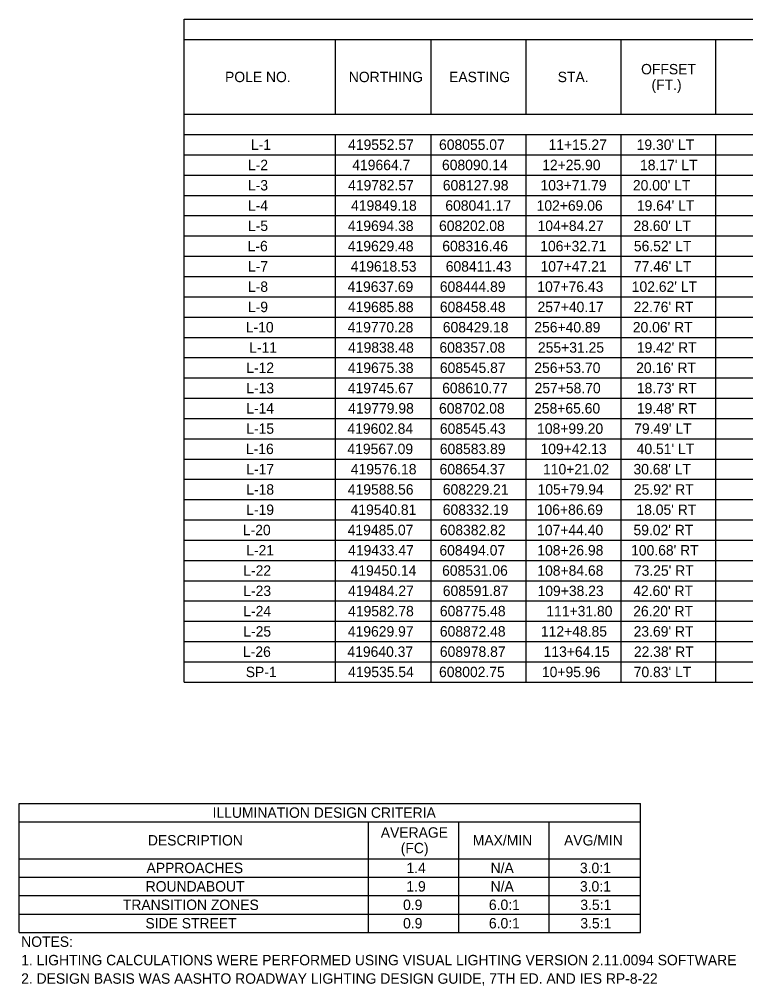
# Model space of a CAD drawing. Extents: x 0.17 to 2.79, y 0.05 to 1.72.
# Drawn here: x 0.169 to 0.862, y 0.144 to 1.066 of the extents above; entities that cross this region are included whole.
import ezdxf

# ---------------------------------------------------------------- set-up
doc = ezdxf.new("R2010")
doc.units = 0
doc.layers.add('Default', color=7, linetype='Continuous')
doc.layers.add('No_Plot', color=7, linetype='Continuous')

msp = doc.modelspace()

# ---------------------------------------------------------------- linework, layer by layer
at = {"layer": 'Default'}
for p, q in [((0.32609, 1.06625), (2.52066, 1.06625)), ((0.32609, 0.43358), (0.32609, 1.06625)), ((0.32609, 1.04689), (2.52066, 1.04689)), ((0.4704, 0.97562), (0.4704, 1.04689)), ((0.56192, 0.97562), (0.56192, 1.04689)), ((0.65255, 0.97562), (0.65255, 1.04689)), ((0.74318, 0.97562), (0.74318, 1.04689)), ((0.83382, 0.97562), (0.83382, 1.04689)), ((0.32609, 0.97562), (2.52066, 0.97562)), ((0.32609, 0.95626), (2.52066, 0.95626)), ((0.4704, 0.43358), (0.4704, 0.95626)), ((0.56192, 0.43358), (0.56192, 0.95626)), ((0.65255, 0.43358), (0.65255, 0.95626)), ((0.74318, 0.43358), (0.74318, 0.95626)), ((0.83382, 0.43358), (0.83382, 0.95626)), ((0.32609, 0.9369), (2.52066, 0.9369)), ((0.32609, 0.91754), (2.52066, 0.91754)), ((0.32609, 0.89819), (2.52066, 0.89819)), ((0.32609, 0.87883), (2.52066, 0.87883)), ((0.32609, 0.85947), (2.52066, 0.85947)), ((0.32609, 0.84011), (2.52066, 0.84011)), ((0.32609, 0.82075), (2.52066, 0.82075)), ((0.32609, 0.80139), (2.52066, 0.80139)), ((0.32609, 0.78203), (2.52066, 0.78203)), ((0.32609, 0.76268), (2.52066, 0.76268)), ((0.32609, 0.74332), (2.52066, 0.74332)), ((0.32609, 0.72396), (2.52066, 0.72396)), ((0.32609, 0.7046), (2.52066, 0.7046)), ((0.32609, 0.68524), (2.52066, 0.68524)), ((0.32609, 0.66588), (2.52066, 0.66588)), ((0.32609, 0.64652), (2.52066, 0.64652)), ((0.32609, 0.62716), (2.52066, 0.62716)), ((0.32609, 0.60781), (2.52066, 0.60781)), ((0.32609, 0.58845), (2.52066, 0.58845)), ((0.32609, 0.56909), (2.52066, 0.56909)), ((0.32609, 0.54973), (2.52066, 0.54973)), ((0.32609, 0.53037), (2.52066, 0.53037)), ((0.32609, 0.51101), (2.52066, 0.51101)), ((0.32609, 0.49165), (2.52066, 0.49165)), ((0.32609, 0.4723), (2.52066, 0.4723)), ((0.32609, 0.45294), (2.52066, 0.45294)), ((0.32609, 0.43358), (2.52066, 0.43358)), ((0.16857, 0.31777), (0.76164, 0.31777)), ((0.16857, 0.19458), (0.16857, 0.31777)), ((0.76164, 0.19458), (0.76164, 0.31777)), ((0.16857, 0.30017), (0.76164, 0.30017)), ((0.50206, 0.19458), (0.50206, 0.30017)), ((0.5883, 0.19458), (0.5883, 0.30017)), ((0.67453, 0.19458), (0.67453, 0.30017)), ((0.16857, 0.26497), (0.76164, 0.26497)), ((0.16857, 0.24737), (0.76164, 0.24737)), ((0.16857, 0.22978), (0.76164, 0.22978)), ((0.16857, 0.21218), (0.76164, 0.21218)), ((0.16857, 0.19458), (0.76164, 0.19458))]:
    msp.add_line(p, q, dxfattribs=at)
at = {"layer": 'No_Plot'}
for p, q in [((0.32609, 1.06625), (0.32609, 1.06625)), ((0.16857, 0.31777), (0.16857, 0.31777))]:
    msp.add_line(p, q, dxfattribs=at)

# ---------------------------------------------------------------- texts
at = {"layer": 'Default'}
for s, height, p in [('POLE NO.', 0.009927, (0.36503, 1.00629)), ('NORTHING', 0.009927, (0.48321, 1.00629)), ('EASTING', 0.009927, (0.57897, 1.00629)), ('STA.', 0.009927, (0.6827, 1.00629)), ('OFFSET', 0.009927, (0.76235, 1.01374)), (' (FT.)', 0.009927, (0.76861, 0.99885)), ('L-1', 0.009927, (0.38973, 0.94162)), ('419552.57', 0.009927, (0.48255, 0.94162)), ('608055.07', 0.009927, (0.5694, 0.94162)), ('11+15.27', 0.009927, (0.67395, 0.94162)), ("19.30' LT", 0.009927, (0.75813, 0.94162)), ('L-2', 0.009927, (0.38691, 0.92226)), ('419664.7', 0.009927, (0.48653, 0.92226)), ('608090.14', 0.009927, (0.57221, 0.92226)), ('12+25.90', 0.009927, (0.66789, 0.92226)), ("18.17' LT", 0.009927, (0.76134, 0.92226)), ('L-3', 0.009927, (0.38691, 0.9029)), ('419782.57', 0.009927, (0.48255, 0.9029)), ('608127.98', 0.009927, (0.57299, 0.9029)), ('103+71.79', 0.009927, (0.66625, 0.9029)), ("20.00' LT", 0.009927, (0.75454, 0.9029)), ('L-4', 0.009927, (0.38691, 0.88354)), ('419849.18', 0.009927, (0.48536, 0.88354)), ('608041.17', 0.009927, (0.57542, 0.88354)), ('102+69.06', 0.009927, (0.66257, 0.88354)), ("19.64' LT", 0.009927, (0.75829, 0.88354)), ('L-5', 0.009927, (0.38691, 0.86418)), ('419694.38', 0.009927, (0.48231, 0.86418)), ('608202.08', 0.009927, (0.5694, 0.86418)), ('104+84.27', 0.009927, (0.66347, 0.86418)), ("28.60' LT", 0.009927, (0.75508, 0.86418)), ('L-6', 0.009927, (0.38664, 0.84483)), ('419629.48', 0.009927, (0.48231, 0.84483)), ('608316.46', 0.009927, (0.57249, 0.84483)), ('106+32.71', 0.009927, (0.66605, 0.84483)), ("56.52' LT", 0.009927, (0.75547, 0.84483)), ('L-7', 0.009927, (0.38691, 0.82547)), ('419618.53', 0.009927, (0.48513, 0.82547)), ('608411.43', 0.009927, (0.57581, 0.82547)), ('107+47.21', 0.009927, (0.66629, 0.82547)), ("77.46' LT", 0.009927, (0.75547, 0.82547)), ('L-8', 0.009927, (0.38691, 0.80611)), ('419637.69', 0.009927, (0.48204, 0.80611)), ('608444.89', 0.009927, (0.57014, 0.80611)), ('107+76.43', 0.009927, (0.66324, 0.80611)), ("102.62' LT", 0.009927, (0.75344, 0.80611)), ('L-9', 0.009927, (0.38687, 0.78675)), ('419685.88', 0.009927, (0.48231, 0.78675)), ('608458.48', 0.009927, (0.57018, 0.78675)), ('257+40.17', 0.009927, (0.66347, 0.78675)), ("22.76' RT", 0.009927, (0.75524, 0.78675)), ('L-10', 0.009927, (0.38484, 0.76739)), ('419770.28', 0.009927, (0.48216, 0.76739)), ('608429.18', 0.009927, (0.57299, 0.76739)), ('256+40.89', 0.009927, (0.66038, 0.76739)), ("20.06' RT", 0.009927, (0.75446, 0.76739)), ('L-11', 0.009927, (0.38809, 0.74803)), ('419838.48', 0.009927, (0.48255, 0.74803)), ('608357.08', 0.009927, (0.56979, 0.74803)), ('255+31.25', 0.009927, (0.66386, 0.74803)), ("19.42' RT", 0.009927, (0.75829, 0.74803)), ('L-12', 0.009927, (0.38527, 0.72867)), ('419675.38', 0.009927, (0.48231, 0.72867)), ('608545.87', 0.009927, (0.57018, 0.72867)), ('256+53.70', 0.009927, (0.66038, 0.72867)), ("20.16' RT", 0.009927, (0.75766, 0.72867)), ('L-13', 0.009927, (0.38527, 0.70931)), ('419745.67', 0.009927, (0.48231, 0.70931)), ('608610.77', 0.009927, (0.57237, 0.70931)), ('257+58.70', 0.009927, (0.66062, 0.70931)), ("18.73' RT", 0.009927, (0.75829, 0.70931)), ('L-14', 0.009927, (0.38527, 0.68996)), ('419779.98', 0.009927, (0.48255, 0.68996)), ('608702.08', 0.009927, (0.5694, 0.68996)), ('258+65.60', 0.009927, (0.66015, 0.68996)), ("19.48' RT", 0.009927, (0.75829, 0.68996)), ('L-15', 0.009927, (0.38527, 0.6706)), ('419602.84', 0.009927, (0.48192, 0.6706)), ('608545.43', 0.009927, (0.57018, 0.6706)), ('108+99.20', 0.009927, (0.66304, 0.6706)), ("79.49' LT", 0.009927, (0.75571, 0.6706)), ('L-16', 0.009927, (0.385, 0.65124)), ('419567.09', 0.009927, (0.48188, 0.65124)), ('608583.89', 0.009927, (0.57014, 0.65124)), ('109+42.13', 0.009927, (0.66629, 0.65124)), ("40.51' LT", 0.009927, (0.75813, 0.65124)), ('L-17', 0.009927, (0.38527, 0.63188)), ('419576.18', 0.009927, (0.48513, 0.63188)), ('608654.37', 0.009927, (0.56995, 0.63188)), ('110+21.02', 0.009927, (0.66871, 0.63188)), ("30.68' LT", 0.009927, (0.75508, 0.63188)), ('L-18', 0.009927, (0.38527, 0.61252)), ('419588.56', 0.009927, (0.48227, 0.61252)), ('608229.21', 0.009927, (0.57299, 0.61252)), ('105+79.94', 0.009927, (0.66347, 0.61252)), ("25.92' RT", 0.009927, (0.75547, 0.61252)), ('L-19', 0.009927, (0.38523, 0.59316)), ('419540.81', 0.009927, (0.48497, 0.59316)), ('608332.19', 0.009927, (0.57296, 0.59316)), ('106+86.69', 0.009927, (0.66273, 0.59316)), ("18.05' RT", 0.009927, (0.7579, 0.59316)), ('L-20', 0.009927, (0.38203, 0.5738)), ('419485.07', 0.009927, (0.48216, 0.5738)), ('608382.82', 0.009927, (0.57018, 0.5738)), ('107+44.40', 0.009927, (0.66304, 0.5738)), ("59.02' RT", 0.009927, (0.75508, 0.5738)), ('L-21', 0.009927, (0.38527, 0.55445)), ('419433.47', 0.009927, (0.48255, 0.55445)), ('608494.07', 0.009927, (0.56979, 0.55445)), ('108+26.98', 0.009927, (0.66324, 0.55445)), ("100.68' RT", 0.009927, (0.75282, 0.55445)), ('L-22', 0.009927, (0.38246, 0.53509)), ('419450.14', 0.009927, (0.48497, 0.53509)), ('608531.06', 0.009927, (0.57233, 0.53509)), ('108+84.68', 0.009927, (0.66324, 0.53509)), ("73.25' RT", 0.009927, (0.75547, 0.53509)), ('L-23', 0.009927, (0.38246, 0.51573)), ('419484.27', 0.009927, (0.48255, 0.51573)), ('608591.87', 0.009927, (0.57299, 0.51573)), ('109+38.23', 0.009927, (0.66347, 0.51573)), ("42.60' RT", 0.009927, (0.75485, 0.51573)), ('L-24', 0.009927, (0.38246, 0.49637)), ('419582.78', 0.009927, (0.48255, 0.49637)), ('608775.48', 0.009927, (0.57018, 0.49637)), ('111+31.80', 0.009927, (0.67187, 0.49637)), ("26.20' RT", 0.009927, (0.75485, 0.49637)), ('L-25', 0.009927, (0.38246, 0.47701)), ('419629.97', 0.009927, (0.48231, 0.47701)), ('608872.48', 0.009927, (0.57018, 0.47701)), ('112+48.85', 0.009927, (0.66668, 0.47701)), ("23.69' RT", 0.009927, (0.75524, 0.47701)), ('L-26', 0.009927, (0.38218, 0.45765)), ('419640.37', 0.009927, (0.48192, 0.45765)), ('608978.87', 0.009927, (0.57018, 0.45765)), ('113+64.15', 0.009927, (0.66926, 0.45765)), ("22.38' RT", 0.009927, (0.75547, 0.45765)), ('SP-1', 0.009927, (0.3848, 0.43829)), ('419535.54', 0.009927, (0.48255, 0.43829)), ('608002.75', 0.009927, (0.5694, 0.43829)), ('10+95.96', 0.009927, (0.66765, 0.43829)), ("70.83' LT", 0.009927, (0.75532, 0.43829)), ('ILLUMINATION DESIGN CRITERIA', 0.0099275, (0.35313, 0.30401)), ('DESCRIPTION', 0.0099275, (0.29134, 0.27761)), ('AVERAGE', 0.009927, (0.51376, 0.28505)), ('MAX/MIN', 0.009927, (0.60159, 0.27761)), ('AVG/MIN', 0.009927, (0.68881, 0.27761)), ('(FC)', 0.009927, (0.53283, 0.27016)), ('APPROACHES', 0.009927, (0.29005, 0.25121)), ('1.4', 0.009927, (0.5383, 0.25121)), ('N/A', 0.009927, (0.61863, 0.25121)), ('3.0:1', 0.009927, (0.70394, 0.25121)), ('ROUNDABOUT', 0.009927, (0.28923, 0.23361)), ('1.9', 0.009927, (0.53826, 0.23361)), ('N/A', 0.009927, (0.61863, 0.23361)), ('3.0:1', 0.009927, (0.70394, 0.23361)), ('TRANSITION ZONES', 0.0099275, (0.26746, 0.21601)), ('0.9', 0.009927, (0.53506, 0.21601)), ('6.0:1', 0.009927, (0.61703, 0.21601)), ('3.5:1', 0.009927, (0.70433, 0.21601)), ('SIDE STREET', 0.0099275, (0.289, 0.19841)), ('0.9', 0.009927, (0.53506, 0.19841)), ('6.0:1', 0.009927, (0.61703, 0.19841)), ('3.5:1', 0.009927, (0.70433, 0.19841)), ('NOTES:', 0.009927, (0.17033, 0.18082)), ('1. LIGHTING CALCULATIONS WERE PERFORMED USING VISUAL LIGHTING VERSION 2.11.0094 SOFTWARE', 0.0099275, (0.17033, 0.16322)), ('2. DESIGN BASIS WAS AASHTO ROADWAY LIGHTING DESIGN GUIDE, 7TH ED. AND IES RP-8-22', 0.0099275, (0.17033, 0.14562))]:
    msp.add_text(s, height=height, dxfattribs=at).set_placement(p)

doc.saveas('drawing.dxf')
